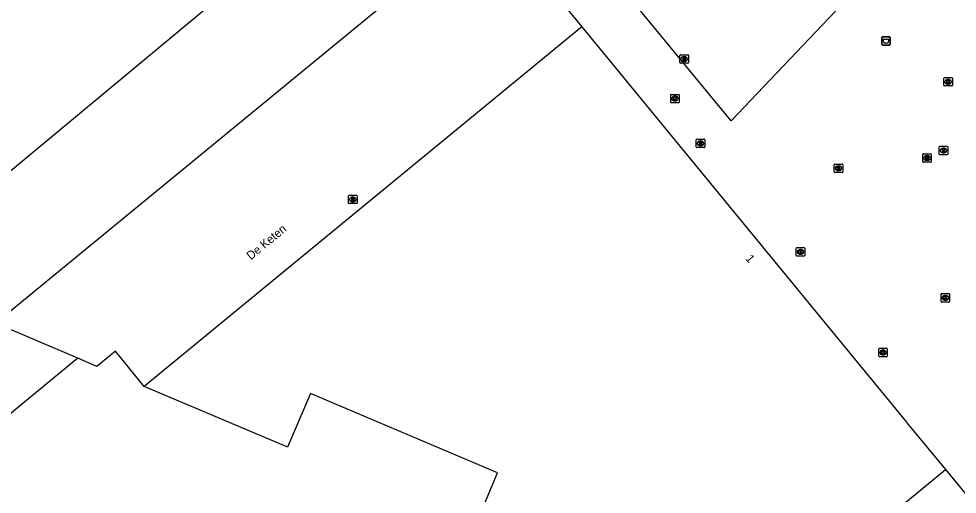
# Model space of a CAD drawing. Extents: x 156141 to 158132, y 385651 to 388399.
# Drawn here: x 156991.7 to 157102.4, y 386265.5 to 386321.6 of the extents above; entities that cross this region are included whole.
import ezdxf

# ---------------------------------------------------------------- set-up
doc = ezdxf.new("R2010")
doc.units = 0
for name, color, linetype in [('IMGEO_Afvalbak', 7, 'Continuous'), ('IMGEO_Brandkraan', 7, 'Continuous'), ('IMGEO_Erf', 7, 'Continuous'), ('IMGEO_Kolk', 7, 'Continuous'), ('IMGEO_Openbare_ruimte_label', 7, 'Continuous'), ('IMGEO_Pand', 7, 'Continuous'), ('IMGEO_Pand_nummerreeks', 7, 'Continuous'), ('IMGEO_Rijbaan_lokaal_gesloten', 7, 'Continuous'), ('IMGEO_Rioolput', 7, 'Continuous')]:
    doc.layers.add(name, color=color, linetype=linetype)

msp = doc.modelspace()

# ---------------------------------------------------------------- linework, layer by layer
at = {"layer": 'IMGEO_Afvalbak'}
for p, q in [((157093.53, 386318.57), (157093.53, 386319.37)), ((157093.53, 386319.37), (157093.53, 386318.57)), ((157093.63, 386319.47), (157094.42, 386319.47)), ((157094.42, 386319.47), (157093.63, 386319.47)), ((157094.52, 386319.37), (157094.52, 386318.57)), ((157094.52, 386318.57), (157094.52, 386319.37)), ((157094.42, 386318.47), (157093.63, 386318.47)), ((157093.63, 386318.47), (157094.42, 386318.47))]:
    msp.add_line(p, q, dxfattribs=at)
msp.add_lwpolyline([(157093.67, 386319.19), (157094.37, 386319.19), (157094.22, 386318.72), (157093.82, 386318.72), (157093.67, 386319.19)], dxfattribs=at)
for centre, start, end in [((157093.63, 386319.37), 90, 180), ((157093.63, 386319.37), 90, 180), ((157094.42, 386319.37), 0, 90), ((157094.42, 386319.37), 360, 90), ((157093.63, 386318.57), 180, 270), ((157093.63, 386318.57), 180, 270), ((157094.42, 386318.57), 270, 0), ((157094.42, 386318.57), 270, 0)]:
    msp.add_arc(centre, 0.1, start, end, dxfattribs=at)
at = {"layer": 'IMGEO_Brandkraan'}
for p, q in [((157071.63, 386306.47), (157071.63, 386307.32)), ((157071.7, 386307.4), (157072.56, 386307.4)), ((157072.12, 386307.17), (157072.14, 386307.17)), ((157072.63, 386307.32), (157072.63, 386306.47)), ((157072.56, 386306.39), (157071.7, 386306.39)), ((157072.14, 386306.62), (157072.11, 386306.62))]:
    msp.add_line(p, q, dxfattribs=at)
for points in [[(157071.63, 386306.47), (157071.63, 386307.32)], [(157071.7, 386307.4), (157072.56, 386307.4)], [(157071.98, 386307.09), (157071.98, 386306.69), (157072.19, 386306.69)], [(157072.21, 386307.09), (157071.98, 386307.09)], [(157072.16, 386307.01), (157072.1, 386307.01), (157072.1, 386306.94)], [(157072.63, 386307.32), (157072.63, 386306.47)], [(157072.56, 386306.39), (157071.7, 386306.39)], [(157072.1, 386306.94), (157072.16, 386306.94)], [(157072.16, 386306.86), (157072.1, 386306.86), (157072.1, 386306.78)], [(157072.1, 386306.78), (157072.16, 386306.78)]]:
    msp.add_lwpolyline(points, dxfattribs=at)
for centre, radius, start, end in [((157071.71, 386307.32), 0.0765, 91.552, 178.448), ((157071.71, 386307.32), 0.0765, 91.552, 178.448), ((157072.16, 386306.98), 0.0379, 267.8285, 90.9355), ((157072.21, 386306.95), 0.145, 59.4692, 91.5367), ((157072.24, 386307), 0.0922, 285.5137, 58.1501), ((157072.55, 386307.32), 0.0765, 1.552, 88.448), ((157072.55, 386307.32), 0.0765, 1.552, 88.448), ((157071.71, 386306.47), 0.0765, 181.552, 268.448), ((157071.71, 386306.47), 0.0765, 181.552, 268.448), ((157072.16, 386306.82), 0.0404, 269.8759, 90.5077), ((157072.2, 386306.95), 0.251, 268.6676, 293.5347), ((157072.24, 386306.81), 0.105, 301.3115, 78.989), ((157072.55, 386306.47), 0.0765, 271.552, 358.448), ((157072.55, 386306.47), 0.0765, 271.552, 358.448)]:
    msp.add_arc(centre, radius, start, end, dxfattribs=at)
for centre, major_axis, ratio, start_param, end_param in [((157072.12, 386306.89), (-0.387, 0.002), 0.722429, 4.712389, 7.853982), ((157072.14, 386306.89), (-0.39, 0.002), 0.717154, 1.570796, 4.712389)]:
    msp.add_ellipse(centre, major_axis=major_axis, ratio=ratio, start_param=start_param, end_param=end_param, dxfattribs=at)
at = {"layer": 'IMGEO_Erf'}
msp.add_lwpolyline([(156998.63, 386281.54), (156977.15, 386263.89)], dxfattribs=at)
at = {"layer": 'IMGEO_Kolk'}
for p, q in [((157100.86, 386313.73), (157100.86, 386314.59)), ((157100.93, 386314.66), (157101.79, 386314.66)), ((157101.79, 386313.66), (157100.93, 386313.66)), ((157101.37, 386313.88), (157101.34, 386313.88)), ((157101.35, 386314.44), (157101.37, 386314.44)), ((157101.86, 386314.59), (157101.86, 386313.73)), ((157068.61, 386311.74), (157068.61, 386312.6)), ((157068.68, 386312.67), (157069.54, 386312.67)), ((157069.61, 386312.6), (157069.61, 386311.74)), ((157069.54, 386311.67), (157068.68, 386311.67)), ((157069.12, 386311.89), (157069.09, 386311.89)), ((157069.1, 386312.45), (157069.12, 386312.45)), ((157087.92, 386303.52), (157087.92, 386304.37)), ((157087.99, 386304.45), (157088.85, 386304.45)), ((157088.41, 386304.23), (157088.43, 386304.23)), ((157088.92, 386304.37), (157088.92, 386303.52)), ((157088.85, 386303.45), (157087.99, 386303.45)), ((157088.43, 386303.67), (157088.41, 386303.67)), ((157083.43, 386293.67), (157083.43, 386294.52)), ((157083.51, 386294.6), (157084.36, 386294.6)), ((157083.92, 386294.37), (157083.95, 386294.37)), ((157083.94, 386293.82), (157083.92, 386293.82)), ((157084.43, 386294.52), (157084.43, 386293.67)), ((157084.36, 386293.59), (157083.51, 386293.59)), ((157100.53, 386288.24), (157100.53, 386289.09)), ((157100.6, 386289.17), (157101.45, 386289.17)), ((157101.01, 386288.95), (157101.04, 386288.95)), ((157101.04, 386288.39), (157101.01, 386288.39)), ((157101.53, 386289.09), (157101.53, 386288.24)), ((157101.45, 386288.17), (157100.6, 386288.17)), ((157093.17, 386281.8), (157093.17, 386282.65)), ((157093.24, 386282.72), (157094.1, 386282.72)), ((157094.17, 386282.65), (157094.17, 386281.8)), ((157094.1, 386281.72), (157093.24, 386281.72)), ((157093.68, 386281.94), (157093.65, 386281.94)), ((157093.66, 386282.5), (157093.68, 386282.5))]:
    msp.add_line(p, q, dxfattribs=at)
for points in [[(157100.86, 386313.73), (157100.86, 386314.59)], [(157100.93, 386314.66), (157101.79, 386314.66)], [(157101.79, 386313.66), (157100.93, 386313.66)], [(157101.18, 386314.36), (157101.3, 386314.36), (157101.3, 386314.21), (157101.43, 386314.36), (157101.6, 386314.36), (157101.45, 386314.21), (157101.6, 386313.96), (157101.45, 386313.96), (157101.37, 386314.12), (157101.3, 386314.06), (157101.3, 386313.96), (157101.18, 386313.96), (157101.18, 386314.36)], [(157101.86, 386314.59), (157101.86, 386313.73)], [(157068.61, 386311.74), (157068.61, 386312.6)], [(157068.68, 386312.67), (157069.54, 386312.67)], [(157069.61, 386312.6), (157069.61, 386311.74)], [(157069.54, 386311.67), (157068.68, 386311.67)], [(157068.93, 386312.37), (157069.05, 386312.37), (157069.05, 386312.22), (157069.18, 386312.37), (157069.35, 386312.37), (157069.2, 386312.22), (157069.35, 386311.97), (157069.2, 386311.97), (157069.12, 386312.13), (157069.05, 386312.07), (157069.05, 386311.97), (157068.93, 386311.97), (157068.93, 386312.37)], [(157087.92, 386303.52), (157087.92, 386304.37)], [(157087.99, 386304.45), (157088.85, 386304.45)], [(157088.24, 386304.15), (157088.36, 386304.15), (157088.36, 386303.99), (157088.49, 386304.15), (157088.66, 386304.15), (157088.51, 386304), (157088.66, 386303.75), (157088.51, 386303.75), (157088.43, 386303.91), (157088.36, 386303.84), (157088.36, 386303.75), (157088.24, 386303.75), (157088.24, 386304.15)], [(157088.92, 386304.37), (157088.92, 386303.52)], [(157088.85, 386303.45), (157087.99, 386303.45)], [(157083.43, 386293.67), (157083.43, 386294.52)], [(157083.51, 386294.6), (157084.36, 386294.6)], [(157083.75, 386294.29), (157083.88, 386294.29), (157083.88, 386294.14), (157084.01, 386294.29), (157084.17, 386294.29), (157084.03, 386294.14), (157084.18, 386293.89), (157084.03, 386293.89), (157083.94, 386294.06), (157083.88, 386293.99), (157083.88, 386293.89), (157083.75, 386293.89), (157083.75, 386294.29)], [(157084.43, 386294.52), (157084.43, 386293.67)], [(157084.36, 386293.59), (157083.51, 386293.59)], [(157100.53, 386288.24), (157100.53, 386289.09)], [(157100.6, 386289.17), (157101.45, 386289.17)], [(157100.85, 386288.87), (157100.97, 386288.87), (157100.97, 386288.71), (157101.1, 386288.87), (157101.26, 386288.87), (157101.12, 386288.72), (157101.27, 386288.47), (157101.12, 386288.47), (157101.03, 386288.63), (157100.97, 386288.56), (157100.97, 386288.47), (157100.85, 386288.47), (157100.85, 386288.87)], [(157101.53, 386289.09), (157101.53, 386288.24)], [(157101.45, 386288.17), (157100.6, 386288.17)], [(157093.17, 386281.8), (157093.17, 386282.65)], [(157093.24, 386282.72), (157094.1, 386282.72)], [(157094.17, 386282.65), (157094.17, 386281.8)], [(157094.1, 386281.72), (157093.24, 386281.72)], [(157093.49, 386282.42), (157093.61, 386282.42), (157093.61, 386282.27), (157093.74, 386282.42), (157093.91, 386282.42), (157093.76, 386282.27), (157093.91, 386282.02), (157093.76, 386282.02), (157093.68, 386282.19), (157093.61, 386282.12), (157093.61, 386282.02), (157093.49, 386282.02), (157093.49, 386282.42)]]:
    msp.add_lwpolyline(points, dxfattribs=at)
for centre, start, end in [((157100.94, 386314.58), 91.552, 178.448), ((157100.94, 386314.58), 91.552, 178.448), ((157100.94, 386313.74), 181.552, 268.448), ((157100.94, 386313.74), 181.552, 268.448), ((157101.78, 386314.58), 1.552, 88.448), ((157101.78, 386314.58), 1.552, 88.448), ((157101.78, 386313.74), 271.552, 358.448), ((157101.78, 386313.74), 271.552, 358.448), ((157068.68, 386312.59), 91.552, 178.448), ((157068.68, 386312.59), 91.552, 178.448), ((157069.53, 386312.59), 1.552, 88.448), ((157069.53, 386312.59), 1.552, 88.448), ((157068.68, 386311.75), 181.552, 268.448), ((157068.68, 386311.75), 181.552, 268.448), ((157069.53, 386311.75), 271.552, 358.448), ((157069.53, 386311.75), 271.552, 358.448), ((157088, 386304.37), 91.552, 178.448), ((157088, 386304.37), 91.552, 178.448), ((157088.84, 386304.37), 1.552, 88.448), ((157088.84, 386304.37), 1.552, 88.448), ((157088, 386303.52), 181.552, 268.448), ((157088, 386303.52), 181.552, 268.448), ((157088.84, 386303.52), 271.552, 358.448), ((157088.84, 386303.52), 271.552, 358.448), ((157083.51, 386294.52), 91.552, 178.448), ((157083.51, 386294.52), 91.552, 178.448), ((157084.36, 386294.52), 1.552, 88.448), ((157084.36, 386294.52), 1.552, 88.448), ((157083.51, 386293.67), 181.552, 268.448), ((157083.51, 386293.67), 181.552, 268.448), ((157084.36, 386293.67), 271.552, 358.448), ((157084.36, 386293.67), 271.552, 358.448), ((157100.6, 386289.09), 91.552, 178.448), ((157100.6, 386289.09), 91.552, 178.448), ((157100.6, 386288.24), 181.552, 268.448), ((157100.6, 386288.24), 181.552, 268.448), ((157101.45, 386289.09), 1.552, 88.448), ((157101.45, 386289.09), 1.552, 88.448), ((157101.45, 386288.24), 271.552, 358.448), ((157101.45, 386288.24), 271.552, 358.448), ((157093.25, 386282.65), 91.552, 178.448), ((157093.25, 386282.65), 91.552, 178.448), ((157094.09, 386282.65), 1.552, 88.448), ((157094.09, 386282.65), 1.552, 88.448), ((157093.25, 386281.8), 181.552, 268.448), ((157093.25, 386281.8), 181.552, 268.448), ((157094.09, 386281.8), 271.552, 358.448), ((157094.09, 386281.8), 271.552, 358.448)]:
    msp.add_arc(centre, 0.0765, start, end, dxfattribs=at)
for centre, major_axis, ratio, start_param, end_param in [((157101.35, 386314.16), (-0.387, 0.002), 0.722429, 4.712389, 7.853982), ((157101.37, 386314.16), (-0.39, 0.002), 0.717154, 1.570796, 4.712389), ((157069.1, 386312.17), (-0.387, 0.002), 0.722429, 4.712389, 7.853982), ((157069.12, 386312.17), (-0.39, 0.002), 0.717154, 1.570796, 4.712389), ((157088.41, 386303.95), (-0.387, 0.002), 0.722429, 4.712389, 7.853982), ((157088.43, 386303.95), (-0.39, 0.002), 0.717154, 1.570796, 4.712389), ((157083.92, 386294.09), (-0.387, 0.002), 0.722429, 4.712389, 7.853982), ((157083.94, 386294.09), (-0.39, 0.002), 0.717154, 1.570796, 4.712389), ((157101.01, 386288.67), (-0.387, 0.002), 0.722429, 4.712389, 7.853982), ((157101.04, 386288.67), (-0.39, 0.002), 0.717154, 1.570796, 4.712389), ((157093.66, 386282.22), (-0.387, 0.002), 0.722429, 4.712389, 7.853982), ((157093.68, 386282.22), (-0.39, 0.002), 0.717154, 1.570796, 4.712389)]:
    msp.add_ellipse(centre, major_axis=major_axis, ratio=ratio, start_param=start_param, end_param=end_param, dxfattribs=at)
at = {"layer": 'IMGEO_Pand'}
for points in [[(157017.94, 386334.89), (157022.13, 386329.74), (156975.52, 386291.04)], [(156998.63, 386281.54), (156988.88, 386285.67), (157047.4, 386333.71), (157053.34, 386326.49)], [(157053.34, 386326.49), (157058.14, 386320.65)], [(157058.14, 386320.65), (157006.49, 386278.21)], [(157058.14, 386320.65), (157096.43, 386274), (157096.47, 386273.94), (157101.03, 386268.4)], [(157006.49, 386278.21), (157003.09, 386282.39), (157000.88, 386280.58), (156998.63, 386281.54)], [(157074.57, 386246.6), (157071.77, 386250), (157069.94, 386252.22), (157069.33, 386251.71), (157063.64, 386254.12), (157059.28, 386255.95), (157045.72, 386261.65), (157045.53, 386261.74), (157048.17, 386268.03), (157026.09, 386277.37), (157023.4, 386271.07), (157023.24, 386271.13), (157006.49, 386278.21)], [(157101.03, 386268.4), (157116.18, 386250), (157129.97, 386233.24), (157121.99, 386226.68), (157108.04, 386232.54), (157103.35, 386234.51), (157086.61, 386241.54), (157086.51, 386241.58), (157074.57, 386246.6)], [(157074.57, 386246.6), (157078.7, 386250), (157101.03, 386268.4)]]:
    msp.add_lwpolyline(points, dxfattribs=at)
at = {"layer": 'IMGEO_Rijbaan_lokaal_gesloten'}
msp.add_lwpolyline([(157101.91, 386337.09), (157075.75, 386309.54), (157060.07, 386328.6)], dxfattribs=at)
at = {"layer": 'IMGEO_Rioolput'}
for p, q in [((157069.7, 386316.42), (157069.7, 386317.27)), ((157069.77, 386317.34), (157070.62, 386317.34)), ((157070.18, 386317.12), (157070.21, 386317.12)), ((157070.7, 386317.27), (157070.7, 386316.42)), ((157070.62, 386316.34), (157069.77, 386316.34)), ((157070.21, 386316.56), (157070.18, 386316.56)), ((157100.31, 386305.62), (157100.31, 386306.47)), ((157100.38, 386306.55), (157101.23, 386306.55)), ((157100.8, 386306.33), (157100.82, 386306.33)), ((157101.31, 386306.47), (157101.31, 386305.62)), ((157098.37, 386304.74), (157098.37, 386305.59)), ((157098.44, 386305.66), (157099.29, 386305.66)), ((157098.85, 386305.44), (157098.88, 386305.44)), ((157098.88, 386304.88), (157098.85, 386304.88)), ((157099.37, 386305.59), (157099.37, 386304.74)), ((157101.23, 386305.55), (157100.38, 386305.55)), ((157100.82, 386305.77), (157100.79, 386305.77)), ((157099.29, 386304.66), (157098.44, 386304.66)), ((157030.6, 386299.85), (157030.6, 386300.7)), ((157030.68, 386300.78), (157031.53, 386300.78)), ((157031.09, 386300.56), (157031.11, 386300.56)), ((157031.6, 386300.7), (157031.6, 386299.85)), ((157031.53, 386299.78), (157030.68, 386299.78)), ((157031.11, 386300), (157031.09, 386300))]:
    msp.add_line(p, q, dxfattribs=at)
for points in [[(157069.7, 386316.42), (157069.7, 386317.27)], [(157069.77, 386317.34), (157070.62, 386317.34)], [(157070.29, 386317.04), (157070.03, 386317.04), (157070.03, 386316.64)], [(157070.7, 386317.27), (157070.7, 386316.42)], [(157070.62, 386316.34), (157069.77, 386316.34)], [(157070.03, 386316.64), (157070.16, 386316.64), (157070.16, 386316.8), (157070.17, 386316.8)], [(157070.21, 386316.96), (157070.16, 386316.96), (157070.16, 386316.88)], [(157070.16, 386316.88), (157070.21, 386316.88)], [(157070.21, 386316.77), (157070.29, 386316.64), (157070.43, 386316.64), (157070.36, 386316.77)], [(157100.31, 386305.62), (157100.31, 386306.47)], [(157100.38, 386306.55), (157101.23, 386306.55)], [(157100.9, 386306.25), (157100.64, 386306.25), (157100.64, 386305.85)], [(157100.64, 386305.85), (157100.77, 386305.85), (157100.77, 386306.01), (157100.78, 386306.01)], [(157100.82, 386306.17), (157100.77, 386306.17), (157100.77, 386306.09)], [(157100.77, 386306.09), (157100.82, 386306.09)], [(157100.83, 386305.98), (157100.9, 386305.85), (157101.04, 386305.85), (157100.97, 386305.97)], [(157101.31, 386306.47), (157101.31, 386305.62)], [(157098.37, 386304.74), (157098.37, 386305.59)], [(157098.44, 386305.66), (157099.29, 386305.66)], [(157098.96, 386305.36), (157098.7, 386305.36), (157098.7, 386304.96)], [(157098.7, 386304.96), (157098.83, 386304.96), (157098.83, 386305.13), (157098.84, 386305.13)], [(157098.88, 386305.28), (157098.83, 386305.28), (157098.83, 386305.2)], [(157098.83, 386305.2), (157098.88, 386305.2)], [(157098.88, 386305.1), (157098.96, 386304.96), (157099.1, 386304.96), (157099.03, 386305.09)], [(157099.37, 386305.59), (157099.37, 386304.74)], [(157101.23, 386305.55), (157100.38, 386305.55)], [(157099.29, 386304.66), (157098.44, 386304.66)], [(157030.6, 386299.85), (157030.6, 386300.7)], [(157030.68, 386300.78), (157031.53, 386300.78)], [(157031.19, 386300.47), (157030.94, 386300.48), (157030.94, 386300.08)], [(157031.12, 386300.4), (157031.06, 386300.4), (157031.06, 386300.31)], [(157031.6, 386300.7), (157031.6, 386299.85)], [(157031.53, 386299.78), (157030.68, 386299.78)], [(157030.94, 386300.08), (157031.06, 386300.08), (157031.06, 386300.24), (157031.07, 386300.24)], [(157031.06, 386300.31), (157031.11, 386300.31)], [(157031.12, 386300.21), (157031.19, 386300.08), (157031.33, 386300.08), (157031.27, 386300.2)]]:
    msp.add_lwpolyline(points, dxfattribs=at)
for centre, radius, start, end in [((157069.77, 386317.27), 0.0765, 91.552, 178.448), ((157069.77, 386317.27), 0.0765, 91.552, 178.448), ((157070.28, 386316.93), 0.109, 350.3612, 89.416), ((157070.62, 386317.27), 0.0765, 1.552, 88.448), ((157070.62, 386317.27), 0.0765, 1.552, 88.448), ((157069.77, 386316.42), 0.0765, 181.552, 268.448), ((157069.77, 386316.42), 0.0765, 181.552, 268.448), ((157070.17, 386316.75), 0.0533, 26.0293, 88.6989), ((157070.22, 386316.86), 0.0964, 77.0061, 93.1865), ((157070.19, 386317.07), 0.19, 274.7715, 282.9687), ((157070.23, 386316.92), 0.0378, 276.6634, 79.6772), ((157070.28, 386316.93), 0.112, 277.5842, 350.9817), ((157070.27, 386316.71), 0.108, 29.5134, 73.7905), ((157070.62, 386316.42), 0.0765, 271.552, 358.448), ((157070.62, 386316.42), 0.0765, 271.552, 358.448), ((157100.38, 386306.47), 0.0765, 91.552, 178.448), ((157100.38, 386306.47), 0.0765, 91.552, 178.448), ((157100.78, 386305.96), 0.0533, 26.0293, 88.6989), ((157100.83, 386306.07), 0.0964, 77.0061, 93.1865), ((157100.8, 386306.28), 0.19, 274.7715, 282.9687), ((157100.84, 386306.13), 0.0378, 276.6634, 79.6772), ((157100.9, 386306.14), 0.109, 350.3612, 89.416), ((157100.89, 386306.14), 0.112, 277.5842, 350.9817), ((157100.88, 386305.92), 0.108, 29.5134, 73.7905), ((157101.23, 386306.47), 0.0765, 1.552, 88.448), ((157101.23, 386306.47), 0.0765, 1.552, 88.448), ((157098.44, 386305.59), 0.0765, 91.552, 178.448), ((157098.44, 386305.59), 0.0765, 91.552, 178.448), ((157098.84, 386305.07), 0.0533, 26.0293, 88.6989), ((157098.89, 386305.19), 0.0964, 77.0061, 93.1865), ((157098.86, 386305.39), 0.19, 274.7715, 282.9687), ((157098.9, 386305.24), 0.0378, 276.6634, 79.6772), ((157098.95, 386305.25), 0.109, 350.3612, 89.416), ((157098.95, 386305.25), 0.112, 277.5842, 350.9817), ((157098.94, 386305.04), 0.108, 29.5134, 73.7905), ((157099.29, 386305.59), 0.0765, 1.552, 88.448), ((157099.29, 386305.59), 0.0765, 1.552, 88.448), ((157100.38, 386305.62), 0.0765, 181.552, 268.448), ((157100.38, 386305.62), 0.0765, 181.552, 268.448), ((157101.23, 386305.62), 0.0765, 271.552, 358.448), ((157101.23, 386305.62), 0.0765, 271.552, 358.448), ((157098.44, 386304.74), 0.0765, 181.552, 268.448), ((157098.44, 386304.74), 0.0765, 181.552, 268.448), ((157099.29, 386304.74), 0.0765, 271.552, 358.448), ((157099.29, 386304.74), 0.0765, 271.552, 358.448), ((157030.68, 386300.7), 0.0765, 91.552, 178.448), ((157030.68, 386300.7), 0.0765, 91.552, 178.448), ((157031.12, 386300.3), 0.0964, 77.0061, 93.1865), ((157031.14, 386300.36), 0.0378, 276.6634, 79.6772), ((157031.19, 386300.36), 0.109, 350.3612, 89.416), ((157031.53, 386300.7), 0.0765, 1.552, 88.448), ((157031.53, 386300.7), 0.0765, 1.552, 88.448), ((157030.68, 386299.85), 0.0765, 181.552, 268.448), ((157030.68, 386299.85), 0.0765, 181.552, 268.448), ((157031.07, 386300.19), 0.0533, 26.0293, 88.6989), ((157031.1, 386300.5), 0.19, 274.7715, 282.9687), ((157031.19, 386300.36), 0.112, 277.5842, 350.9817), ((157031.17, 386300.15), 0.108, 29.5134, 73.7905), ((157031.53, 386299.85), 0.0765, 271.552, 358.448), ((157031.53, 386299.85), 0.0765, 271.552, 358.448)]:
    msp.add_arc(centre, radius, start, end, dxfattribs=at)
for centre, major_axis, ratio, start_param, end_param in [((157070.18, 386316.84), (-0.387, 0.002), 0.722429, 4.712389, 7.853982), ((157070.21, 386316.84), (-0.39, 0.002), 0.717154, 1.570796, 4.712389), ((157100.79, 386306.05), (-0.387, 0.002), 0.722429, 4.712389, 7.853982), ((157100.82, 386306.05), (-0.39, 0.002), 0.717154, 1.570796, 4.712389), ((157098.85, 386305.16), (-0.387, 0.002), 0.722429, 4.712389, 7.853982), ((157098.88, 386305.16), (-0.39, 0.002), 0.717154, 1.570796, 4.712389), ((157031.09, 386300.28), (-0.387, 0.002), 0.722429, 4.712389, 7.853982), ((157031.11, 386300.28), (-0.39, 0.002), 0.717154, 1.570796, 4.712389)]:
    msp.add_ellipse(centre, major_axis=major_axis, ratio=ratio, start_param=start_param, end_param=end_param, dxfattribs=at)

# ---------------------------------------------------------------- texts
at = {"layer": 'IMGEO_Openbare_ruimte_label'}
msp.add_text('De Keten', height=1, rotation=39.4386, dxfattribs=at).set_placement((157019.06, 386293.09))
at = {"layer": 'IMGEO_Pand_nummerreeks'}
msp.add_text('1', height=1, rotation=309.3677, dxfattribs=at).set_placement((157077.38, 386293.27))

doc.saveas('drawing.dxf')
